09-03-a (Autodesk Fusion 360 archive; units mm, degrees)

design "09-03-a" references "09-03-KADOU", "09-03-KOTEI"
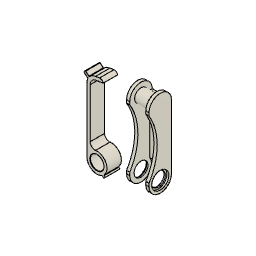
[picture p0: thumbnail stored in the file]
component_insert "コンポーネントの挿入1"
ground "固定1"
component_insert "コンポーネントの挿入3"
ground "固定4"

design "09-03-KADOU"
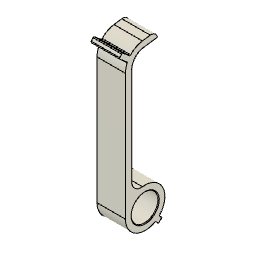
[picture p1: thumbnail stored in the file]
sketch "スケッチ1" plane through (0, 0, 0) normal (1, 0, 0) x axis (0, 0, -1)
  circle C1 centre (0, 0) radius 6.25
  point P1 (0, 0)
  point P2 (0, 0)
  coincident P1 P2
  dimension "d1" diameter C1 = 12.5
extrude "押し出し1" new body sketch "スケッチ1" distance 9
sketch "スケッチ2" plane through (0, 0, 0) normal (1, 0, 0) x axis (0, 0, -1)
  line L1 (-4.25, 0) -> (-4.25, 40)
  line L2 (-6.25, 0) -> (-4.25, 0)
  line L3 (-6.25, 40) -> (-6.25, 0)
  line L4 (3.8647, 44.8349) -> (-0.5915, 44.2086)
  line L5 (3.5864, 46.8155) -> (3.8647, 44.8349)
  line L6 (-0.8698, 46.1892) -> (3.5864, 46.8155)
  circle C1 centre (0, 0) radius 6.25
  arc A1 centre (0, 40) radius 4.25 clockwise from (-4.25, 40) to (-0.5915, 44.2086)
  arc A2 centre (0, 40) radius 6.25 clockwise from (-6.25, 40) to (-0.8698, 46.1892)
  point P1 (0, 0)
  point P8 (0, 40)
  point P12 (0, 40)
  vertical L1
  horizontal L2
  vertical L3
  coincident P1 L2
  tangent L3 C1
  perpendicular L4 L5
  perpendicular L5 L6
  coincident P8 P12
  vertical P1 P8
  tangent L1 A1
  tangent A1 L4
  tangent L3 A2
  dimension "d5" distance L1 L3 = 2
  dimension "d18" distance L4 L6 = 2
  dimension "d21" distance P8 L5 = 4.5
  dimension "d22" angle L1 L4 = 98
  dimension "d54" distance P1 P12 = 40
extrude "押し出し2" add sketch "スケッチ2" profile of L1 L3 C1 distance 9
sketch "スケッチ4" plane through (0, 0, 0) normal (1, 0, 0) x axis (0, 0, -1)
  line L1 (5.3033, -5.3033) -> (0, 0)
  line L2 (4.2426, -6.364) -> (5.3033, -5.3033)
  line L3 (-1.0607, -1.0607) -> (4.2426, -6.364)
  line L4 (0, 0) -> (-1.0607, -1.0607)
  line L5 (-22.5, 0) -> (-1.75, 0)
  point P1 (0, 0)
  point P2 (0, 0)
  perpendicular L1 L2
  parallel L1 L3
  parallel L2 L4
  coincident P1 P2
  dimension "d24" angle L1 L5 = 45
  dimension "d25" distance L2 L4 = 7.5
  dimension "d26" distance L1 L3 = 1.5
extrude "押し出し4" add sketch "スケッチ4" profile of L1 L2 L3 L4 distance 9
joint_origin "JointOrigin1" OffsetX 0 OffsetY 0 OffsetZ 0 AngleZ 0
sketch "スケッチ5" plane through (0, 0, 0) normal (1, 0, 0) x axis (0, 0, -1)
  line L1 (0, 40) -> (-7.2774, 46.1065)
  line L2 (-0.9642, 38.8509) -> (0, 40)
  line L3 (-8.2416, 44.9574) -> (-0.9642, 38.8509)
  line L4 (-7.2774, 46.1065) -> (-8.2416, 44.9574)
  line L5 (0, 22.5) -> (0, 1.75)
  arc A1 centre (0, 40) radius 4.25 clockwise from (-4.25, 40) to (-0.5915, 44.2086)
  point P3 (0, 40)
  point P8 (0, 40)
  perpendicular L1 L2
  parallel L1 L3
  parallel L2 L4
  coincident P3 P8
  dimension "d33" angle L1 L5 = 50
  dimension "d34" distance L1 L3 = 1.5
  dimension "d35" distance L2 L4 = 9.5
extrude "押し出し5" add sketch "スケッチ5" profile of L1 L3 L4 A1 distance 9
fillet "フィレット3" radius 2
sketch "スケッチ6" plane through (0, 43.4339, 6.1042) normal (0, -0.9903, -0.1392) x axis (-1, 0, 0)
  line L1 (-4.5, 10.0669) -> (4.5, 10.0669)
  line L2 (-4.5, 5.5669) -> (-4.5, 10.0669)
  line L3 (4.5, 5.5669) -> (-4.5, 5.5669)
  line L4 (4.5, 10.0669) -> (4.5, 5.5669)
  circle C1 centre (0, 8.0669) radius 0.75
  point P1 (0, 0)
  point P6 (0, 8.0669)
  vertical P1 P6
  dimension "d40" distance L1 P6 = 2
  dimension "d41" diameter C1 = 1.5
extrude "押し出し6" add sketch "スケッチ6" profile of C1 along normal blind 0.7
fillet "フィレット4" radius 0.6
fillet "フィレット5" radius 3
fillet "フィレット6" radius 0.3
hole "穴" HoleDepth 9 HoleDiameter 8.5 TipAngle 118
chamfer "面取り" distance 0.2

design "09-03-KOTEI"
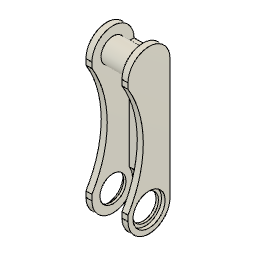
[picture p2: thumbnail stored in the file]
sketch "スケッチ1" plane through (0, 0, 0) normal (1, 0, 0) x axis (0, 0, -1)
  circle C1 centre (0, 40) radius 4
  point P1 (0, 0)
  point P2 (0, 40)
  vertical P1 P2
  dimension "d1" diameter C1 = 8
  dimension "d29" distance P1 P2 = 40
extrude "押し出し1" new body sketch "スケッチ1" + "スケッチ5" profile of S1:C1 distance 10
sketch "スケッチ2" plane through (5, 0, 0) normal (1, 0, 0) x axis (0, 0, -1)
  line L1 (-7, 0) -> (-7, 40)
  line L2 (7, 40) -> (7, 0)
  line L3 (0, 0) -> (0, 40)
  circle C1 centre (0, 40) radius 4
  arc A1 centre (0, 0) radius 7 clockwise from (7, 0) to (-7, 0)
  arc A2 centre (0, 40) radius 7 clockwise from (-7, 40) to (7, 40)
  point P7 (0, 40)
  point P9 (0, 40)
  point P8 (0, 0)
  tangent L1 A1
  tangent A1 L2
  parallel L1 L2
  tangent L2 A2
  tangent L1 A2
  vertical L3
  coincident P7 P9
  concentric C1 A2
  dimension "d4" radius A2 = 7
  dimension "d5" distance P7 P8 = 40
extrude "押し出し2" add sketch "スケッチ2" profile of C1 L1 A1 L2 A2 along normal blind 2
mirror "ミラー" sketch "スケッチ5" mirrorStitchTolerance 0.1
sketch "スケッチ3" plane through (0, 0, 0) normal (1, 0, 0) x axis (0, 0, -1)
  line L1 (7, 40) -> (5.4, 40)
  line L2 (7, 0) -> (7, 40)
  line L3 (5.4, 0) -> (7, 0)
  line L4 (5.4, 40) -> (5.4, 0)
  point P3 (7, 40)
  point P6 (7, 40)
  point P4 (7, 0)
  point P7 (7, 0)
  horizontal L1
  vertical L2
  horizontal L3
  vertical L4
  coincident P3 P6
  coincident P4 P7
  dimension "d10" distance L2 L4 = 1.6
extrude "押し出し3" add sketch "スケッチ3" distance 10
sketch "スケッチ4" plane through (0, 0, 0) normal (1, 0, 0) x axis (0, 0, -1)
  circle C1 centre (-36.9324, 20) radius 35
  arc A1 centre (0, 40) radius 7 clockwise from (-7, 40) to (7, 40)
  arc A2 centre (0, 0) radius 7 clockwise from (7, 0) to (-7, 0)
  tangent C1 A1
  tangent C1 A2
  dimension "d13" diameter C1 = 70
extrude "押し出し4" cut sketch "スケッチ4" profile of C1 no distance stored
sketch "スケッチ5" plane through (0, 0, 0) normal (1, 0, 0) x axis (0, 0, -1)
  circle C1 centre (0, 0) radius 6.5
  arc A1 centre (0, 0) radius 7 clockwise from (7, 0) to (-7, 0)
  concentric C1 A1
  dimension "d15" diameter C1 = 13
extrude "押し出し5" cut sketch "スケッチ5" profile of C1 distance 10
chamfer "面取り" distance 0.2
hole "穴1" HoleDepth 2 HoleDiameter 8.7 TipAngle 118 CBDepth 1.2 CBDiameter 10.7
hole "穴2" HoleDepth 2 HoleDiameter 8.7 TipAngle 118 CBDepth 1.2 CBDiameter 10.7
joint_origin "JointOrigin1" sketch "スケッチ5" OffsetX 0 OffsetY 0 OffsetZ 0 AngleZ 0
